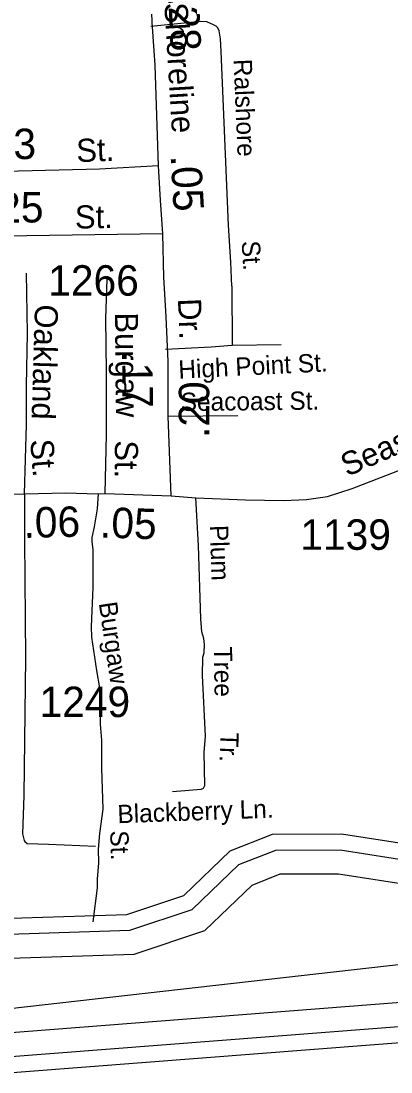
# Model space of a CAD drawing. Extents: x 2104537 to 2336408, y 34176 to 229611.
# Drawn here: x 2204854 to 2206373, y 60476 to 64790 of the extents above; entities that cross this region are included whole.
import ezdxf

# ---------------------------------------------------------------- set-up
doc = ezdxf.new("R2010")
doc.units = 0
for name, color, linetype in [('Exist Boundary Political City Limit New', 7, 'Continuous'), ('Exist Hydrographic Buffer Line', 7, 'Continuous'), ('Exist Hydrographic Creek Single Shore', 7, 'Continuous'), ('Exist Road Non-System Type 51', 7, 'Continuous'), ('Exist Road Non-System Type 51 Label', 7, 'Continuous'), ('Exist Road Secondary Mileage Hundredths English Label', 7, 'Continuous'), ('Exist Road Secondary Type 51 Attributed', 7, 'Continuous'), ('Exist Road Secondary Type 51 Label', 7, 'Continuous'), ('Exist Road Secondary Type 51 Number Label', 7, 'Continuous'), ('Map Preparation Boundary City Limit Buffer Line', 7, 'Continuous')]:
    doc.layers.add(name, color=color, linetype=linetype)

msp = doc.modelspace()

# ---------------------------------------------------------------- linework, layer by layer
at = {"layer": 'Exist Boundary Political City Limit New'}
msp.add_lwpolyline([(2190435.2, 57321.5), (2190540.2, 58145), (2190701.5, 58827.2), (2190746.5, 58940.8), (2190860.5, 59043.3), (2191017.2, 59149.3), (2191214, 59250.7), (2191462.8, 59339.5), (2191837.2, 59387.5), (2192241.2, 59378.3), (2192516.2, 59324.1), (2192761.5, 59327.3), (2202125.8, 60433.4), (2206426.8, 60920)], dxfattribs=at)
at = {"layer": 'Exist Hydrographic Buffer Line'}
for points in [[(2200352.9, 60413.3), (2200648.3, 60527.5), (2200777.6, 60664.3), (2200817.8, 60662.1), (2200992.3, 60518.7), (2201168.2, 60442.8), (2201499.7, 60482.3), (2201857.1, 60593.7), (2202781.2, 60715.6), (2203533.9, 60737.4), (2203757.4, 60793), (2204158, 61019.1), (2204280.6, 61056.7), (2204596.8, 61034.6), (2205300.7, 61057.8), (2205556.7, 61143.1), (2205749, 61327.7), (2205899.6, 61387.2), (2206164.9, 61388.3), (2206477.8, 61339.1)], [(2200288.2, 60197.9), (2200324.3, 60264.1), (2200402.6, 60326.9), (2200704.5, 60443.7), (2200802.5, 60547.3), (2200940.5, 60433.8), (2201153.5, 60341.9), (2201520.3, 60385.7), (2201878.3, 60497.2), (2202789, 60617.4), (2203547.4, 60639.3), (2203794.1, 60700.7), (2204197, 60928.2), (2204291.9, 60957.2), (2204595, 60936.1), (2205318.2, 60959.9), (2205608.9, 61056.7), (2205803.2, 61243.3), (2205918.5, 61288.9), (2206157.4, 61289.8), (2206476, 61239.7)], [(2201961.3, 60309.1), (2202378.1, 60399.1), (2203671.1, 60549.6), (2206519.3, 60770.3), (2207299.9, 60859), (2208310.5, 61056.9), (2208890.6, 61096.9), (2209413.3, 61056.4)], [(2202018.9, 60220.9), (2202394.2, 60301.9), (2203680.6, 60451.6), (2206528.7, 60672.3), (2207315, 60761.7), (2208323.4, 60959.1), (2208890.2, 60998.2), (2209404.1, 60958.4)]]:
    msp.add_lwpolyline(points, dxfattribs=at)
at = {"layer": 'Exist Hydrographic Creek Single Shore'}
for points in [[(2200319.8, 60470.8), (2200610.8, 60583.3), (2200750.8, 60731.5), (2200842.9, 60726.5), (2201026.8, 60575.3), (2201177.9, 60510), (2201485.9, 60546.8), (2201842.9, 60658), (2202775.9, 60781.1), (2203525, 60802.7), (2203732.9, 60854.5), (2204131.9, 61079.8), (2204273, 61123), (2204598, 61100.3), (2205289, 61123.1), (2205522, 61200.6), (2205712.9, 61384), (2205887, 61452.8), (2206169.9, 61453.9), (2206478.9, 61405.3)], [(2202057.3, 60162), (2202405, 60237.1), (2203686.9, 60386.3), (2206534.9, 60607), (2207325, 60696.8), (2208332, 60893.9), (2208889.9, 60932.4), (2209398.5, 60893)]]:
    msp.add_lwpolyline(points, dxfattribs=at)
at = {"layer": 'Exist Road Non-System Type 51'}
for points in [[(2205719, 63702.1), (2205715.7, 63800.2), (2205706.2, 63951.9), (2205676, 64665.8), (2205673.4, 64717.7), (2205667.1, 64749.6), (2205661.8, 64761.8), (2205655, 64769.5), (2205644.6, 64775.3), (2205616.6, 64787), (2205592.7, 64788.8), (2205387, 64768.4)], [(2205719, 63702.1), (2205721.1, 63460.1)], [(2205447.7, 63443.2), (2205634.7, 63452.5)], [(2205634.7, 63452.5), (2205721.1, 63460.1), (2205921.6, 63462.3)], [(2205458, 63168.2), (2205743.9, 63170.5)], [(2205170.5, 62848.8), (2205167.4, 62787.5), (2205155.1, 62713.6), (2205144.8, 62670.5), (2205144.7, 62652.4), (2205149.4, 62620.5), (2205149.3, 62464.7), (2205142.3, 62304.7), (2205144.1, 62260.4), (2205163.8, 62124.5), (2205176.8, 62053), (2205178.9, 61903.1), (2205184.8, 61838.3), (2205185.2, 61723.2), (2205189.9, 61555.4), (2205176.8, 61455), (2205171.6, 61390.7)], [(2205476, 61627.7), (2205594, 61636.9), (2205602.9, 61641.3), (2205609, 61651.4), (2205606.1, 61786.9), (2205611.7, 61855), (2205598.7, 62103), (2205600.8, 62179.4), (2205605.8, 62197), (2205607.1, 62231.1), (2205604.9, 62255.1), (2205596.3, 62282.2), (2205592.1, 62336.7), (2205582.8, 62636.8), (2205572.4, 62832.5)], [(2205171.6, 61390.7), (2205172.2, 61335), (2205167.3, 61266.8), (2205167.2, 61231.7), (2205149.5, 61092.6)]]:
    msp.add_lwpolyline(points, dxfattribs=at)
at = {"layer": 'Exist Road Secondary Type 51 Attributed'}
msp.add_line((2205200.4, 62851.1), (2205470.2, 62841.7), dxfattribs=at)
for points in [[(2205419.3, 64196), (2205405.6, 64609.7), (2205392, 64785.4), (2205386.1, 64980.5), (2205380.3, 65091.7), (2205368.6, 65480.1), (2205362.3, 65677.3)], [(2205419.3, 64196), (2205176.8, 64182.6), (2204789.2, 64172.6), (2204213.8, 64164.8)], [(2205436.8, 63917), (2205427.1, 64055.5), (2205419.3, 64196)], [(2205470.2, 62841.7), (2205572.4, 62832.5), (2205776.2, 62824.2), (2205932.3, 62822.2), (2206025.9, 62826.1), (2206111.7, 62837.8), (2206213.2, 62871), (2206394.6, 62941.3), (2206611.1, 63034.9), (2206853, 63155.9), (2207038.3, 63251.5), (2207163.3, 63325.8), (2207366.3, 63440.3), (2207497.5, 63511.6), (2207711.2, 63637.9), (2207908.2, 63745.2), (2208179.4, 63897.5), (2208300.3, 63961.9), (2208388.1, 64000.9), (2208452.5, 64032.5)], [(2205436.8, 63917), (2204133.8, 63897.5)], [(2205470.2, 62841.7), (2205458, 63168.2), (2205458.3, 63392), (2205450.5, 63575.5), (2205440.7, 63739.4), (2205436.8, 63917)], [(2204868.3, 62849), (2204877, 63134.4), (2204877, 63292.5), (2204880.9, 63509.1), (2204877, 63755)], [(2205200.4, 62851.1), (2205205.1, 63093.2), (2205205.2, 63351.2), (2205203.1, 63568.9), (2205208.5, 63731.2)], [(2203436.7, 62800.1), (2203656.4, 62813), (2203848.5, 62821.4), (2203900.3, 62822.4), (2204062.2, 62830.4), (2204254.2, 62832.9), (2204384.3, 62840.6), (2204868.3, 62849)], [(2204868.3, 62849), (2204869, 62661), (2204873.1, 62176.3), (2204865.3, 61610.4), (2204860.8, 61453.8), (2204867.2, 61426.8), (2204870.4, 61421.7), (2204880.1, 61413.4), (2204966.7, 61411.3), (2205159.8, 61403.5)], [(2204868.3, 62849), (2205036.4, 62853), (2205170.5, 62848.8), (2205200.4, 62851.1)]]:
    msp.add_lwpolyline(points, dxfattribs=at)
at = {"layer": 'Map Preparation Boundary City Limit Buffer Line'}
msp.add_lwpolyline([(2190435.2, 57321.5), (2190540.2, 58145), (2190701.5, 58827.2), (2190746.5, 58940.8), (2190860.5, 59043.3), (2191017.2, 59149.3), (2191214, 59250.7), (2191462.8, 59339.5), (2191837.2, 59387.5), (2192241.2, 59378.3), (2192516.2, 59324.1), (2192761.5, 59327.3), (2202125.8, 60433.4), (2206426.8, 60920)], dxfattribs=at)

# ---------------------------------------------------------------- texts
at = {"layer": 'Exist Road Non-System Type 51 Label'}
for s, rotation, p in [('Ralshore', 272.4231, (2205726.6, 64633)), ('St.', 273.5986, (2205759.6, 63886.4)), ('High Point St.', 2.8723, (2205502, 63321.5)), ('Seacoast St.', 0.5913, (2205510.1, 63189.3)), ('Plum ', 271.7774, (2205629.4, 62720.1)), ('Burgaw', 278.2461, (2205173.4, 62400.9)), ('Tree ', 271.0085, (2205645.5, 62221.2)), ('Tr.', 267.9251, (2205673.5, 61871.5)), ('Blackberry Ln.', 2.0843, (2205251.4, 61497)), ('St.', 271.5854, (2205220.2, 61466.8))]:
    msp.add_text(s, height=75, rotation=rotation, dxfattribs=at).set_placement(p)
at = {"layer": 'Exist Road Secondary Mileage Hundredths English Label'}
for s, rotation, p in [('.28', 273.0113, (2205457.7, 64895.5)), ('.23', 0.7772, (2204684.4, 64221)), ('.05', 273.1786, (2205468.3, 64237.6)), ('.25', 0.8581, (2204715.1, 63960.6)), ('.17', 270.568, (2205268.9, 63433.9)), ('.20', 89.9276, (2205626.7, 63078.8)), ('.06', 1.3577, (2204865.9, 62668.1)), ('.05', 357.9917, (2205177, 62670.4))]:
    msp.add_text(s, height=125, rotation=rotation, dxfattribs=at).set_placement(p)
at = {"layer": 'Exist Road Secondary Type 51 Label'}
for s, rotation, p in [('Shoreline', 273.3717, (2205442.5, 64863.3)), ('St.', 2.2333, (2205083, 64210.6)), ('St.', 0.7652, (2205076.2, 63938.2)), ('Dr.', 272.389, (2205498.1, 63650.4)), ('Oakland', 268.2804, (2204911.9, 63628)), ('Burgaw', 270.568, (2205239.7, 63593.7)), ('Seashore', 23.8116, (2206193, 62918.6)), ('St.', 274.5161, (2204892, 63070.3)), ('St.', 269.9019, (2205239.6, 63069))]:
    msp.add_text(s, height=95, rotation=rotation, dxfattribs=at).set_placement(p)
at = {"layer": 'Exist Road Secondary Type 51 Number Label'}
for s, p in [('1266', (2204966, 63662.8)), ('1139', (2206000.7, 62619.5)), ('1249', (2204930.5, 61932.9))]:
    msp.add_text(s, height=125, dxfattribs=at).set_placement(p)

doc.saveas('drawing.dxf')
